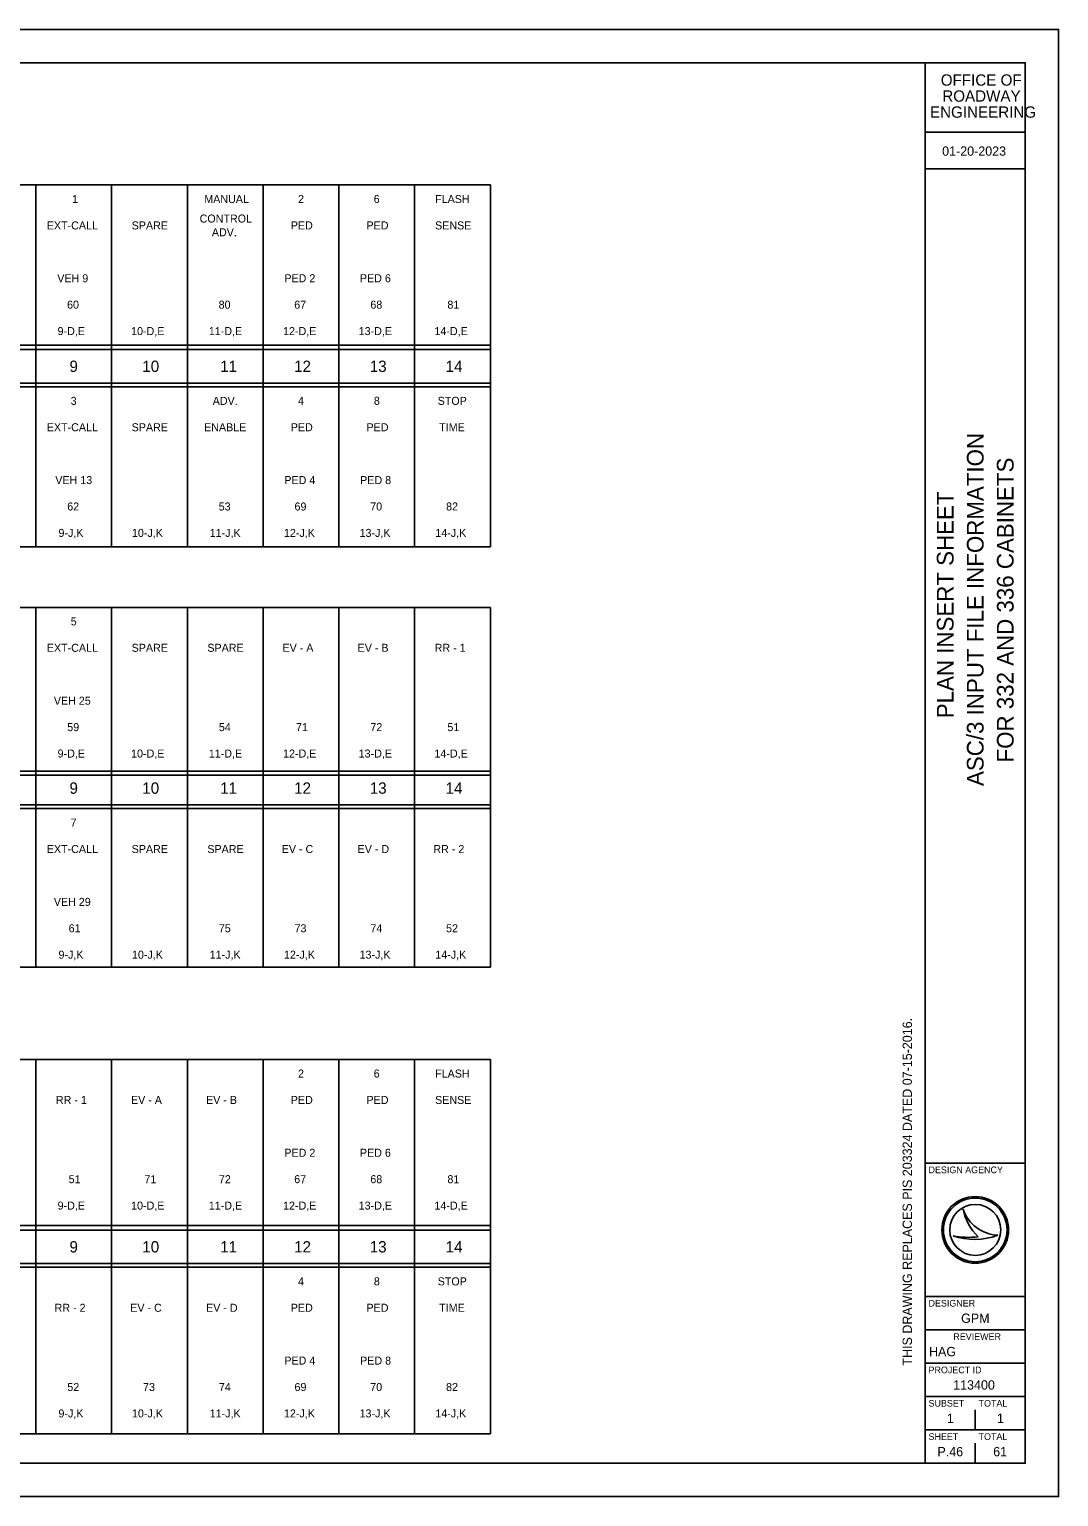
# Model space of a CAD drawing. Extents: x 0 to 34, y -1.2 to 22.
# Drawn here: x 18.57 to 34, y 0 to 22 of the extents above; entities that cross this region are included whole.
import ezdxf

# ---------------------------------------------------------------- set-up
doc = ezdxf.new("R2010")
doc.units = 0
for name, color, linetype in [('SH_Border', 7, 'Continuous'), ('SH_Cut_Line', 7, 'Continuous'), ('SH_Data', 7, 'Continuous'), ('SH_Text', 7, 'Continuous'), ('ST_Text', 7, 'Continuous')]:
    doc.layers.add(name, color=color, linetype=linetype)

msp = doc.modelspace()

# ---------------------------------------------------------------- linework, layer by layer
at = {"layer": 'SH_Border'}
for p, q in [((32, 0.5), (32, 21.5)), ((32, 5), (33.5, 5)), ((32, 3), (33.5, 3)), ((32, 2.5), (33.5, 2.5)), ((32, 2), (33.5, 2)), ((32, 1.5), (33.5, 1.5)), ((32, 1), (33.5, 1))]:
    msp.add_line(p, q, dxfattribs=at)
msp.add_lwpolyline([(1.5, 21.5), (33.5, 21.5), (33.5, 0.5), (1.5, 0.5)], close=True, dxfattribs=at)
at = {"layer": 'SH_Cut_Line'}
msp.add_lwpolyline([(0, 0), (34, 0), (34, 22), (0, 22)], close=True, dxfattribs=at)
at = {"layer": 'SH_Data'}
for p, q in [((32.567, 4.31), (32.567, 4.31)), ((32.75, 4), (32.75, 4)), ((32.417, 3.91), (32.417, 3.91)), ((33.087, 3.919), (33.087, 3.919)), ((32.75, 1), (32.75, 1.3)), ((32.375, 0.675), (32.375, 0.675)), ((32.75, 0.5), (32.75, 0.8))]:
    msp.add_line(p, q, dxfattribs=at)
for radius in [0.5, 0.477, 0.477, 0.382]:
    msp.add_circle((32.75, 4), radius, dxfattribs=at)
for centre, radius, start, end in [((33.116, 4.498), 0.58, 198.9257, 198.9319), ((33.347, 4.47), 0.796, 191.6379, 191.6421), ((33.116, 4.498), 0.58, 198.9319, 267.1657), ((33.347, 4.47), 0.796, 191.6421, 226.0947), ((32.739, 4.87), 1.013, 251.4576, 290.0832), ((32.648, 5.154), 1.266, 259.4964, 259.4995), ((32.739, 4.87), 1.013, 251.4527, 251.4576), ((32.648, 5.154), 1.266, 259.4995, 276.6672)]:
    msp.add_arc(centre, radius, start, end, dxfattribs=at)
at = {"layer": 'SH_Text'}
for p, q in [((32, 20.456), (33.5, 20.456)), ((32, 19.909), (33.5, 19.909))]:
    msp.add_line(p, q, dxfattribs=at)
at = {"layer": 'ST_Text'}
for p, q in [((25.482, 19.667), (5.77, 19.667)), ((18.67, 14.239), (18.67, 19.667)), ((19.805, 14.239), (19.805, 19.667)), ((20.941, 14.239), (20.941, 19.667)), ((22.076, 14.239), (22.076, 19.667)), ((23.212, 14.239), (23.212, 19.667)), ((24.347, 14.239), (24.347, 19.667)), ((25.482, 14.239), (25.482, 19.667)), ((25.482, 17.266), (5.77, 17.266)), ((25.482, 17.199), (5.77, 17.199)), ((25.482, 16.697), (5.77, 16.697)), ((23.945, 16.641), (5.77, 16.641)), ((25.482, 16.641), (5.77, 16.641)), ((25.482, 14.239), (5.77, 14.239)), ((23.945, 13.333), (5.77, 13.333)), ((25.482, 13.333), (5.77, 13.333)), ((18.67, 7.939), (18.67, 13.333)), ((19.805, 7.939), (19.805, 13.333)), ((20.941, 7.939), (20.941, 13.333)), ((22.076, 7.939), (22.076, 13.333)), ((23.212, 7.939), (23.212, 13.333)), ((24.347, 7.939), (24.347, 13.333)), ((25.482, 7.939), (25.482, 13.333)), ((25.482, 10.876), (5.77, 10.876)), ((25.482, 10.819), (5.77, 10.819)), ((25.482, 10.373), (5.77, 10.373)), ((25.482, 10.317), (5.77, 10.317)), ((25.482, 7.939), (5.77, 7.939)), ((25.482, 6.555), (5.77, 6.555)), ((18.67, 0.94), (18.67, 6.555)), ((19.805, 0.94), (19.805, 6.555)), ((20.941, 0.94), (20.941, 6.555)), ((22.076, 0.94), (22.076, 6.555)), ((23.212, 0.94), (23.212, 6.555)), ((24.347, 0.94), (24.347, 6.555)), ((25.482, 0.94), (25.482, 6.555)), ((25.482, 4.064), (5.77, 4.064)), ((25.482, 3.998), (5.77, 3.998)), ((25.482, 3.495), (5.77, 3.495)), ((25.482, 3.439), (5.77, 3.439)), ((25.482, 0.94), (5.77, 0.94))]:
    msp.add_line(p, q, dxfattribs=at)

# ---------------------------------------------------------------- texts
at = {"layer": 'SH_Data'}
for s, p in [('ASC/3 INPUT FILE INFORMATION', (32.875, 10.655)), ('FOR 332 AND 336 CABINETS', (33.325, 11.008)), ('PLAN INSERT SHEET', (32.425, 11.671))]:
    msp.add_text(s, height=0.25, rotation=90, dxfattribs=at).set_placement(p)
for s, height, p in [('DESIGN AGENCY', 0.1, (32.05, 4.85)), ('DESIGNER', 0.1, (32.05, 2.85)), ('GPM', 0.14, (32.538, 2.605)), ('REVIEWER', 0.1, (32.422, 2.35)), ('HAG', 0.14, (32.057, 2.105)), ('PROJECT ID', 0.1, (32.05, 1.85)), ('113400', 0.14, (32.419, 1.605)), ('SUBSET', 0.1, (32.05, 1.35)), ('TOTAL', 0.1, (32.8, 1.35)), ('1', 0.14, (32.325, 1.105)), ('1', 0.14, (33.075, 1.105)), ('SHEET', 0.1, (32.05, 0.85)), ('TOTAL', 0.1, (32.8, 0.85)), ('P.46', 0.14, (32.183, 0.605)), ('61', 0.14, (33.019, 0.605))]:
    msp.add_text(s, height=height, dxfattribs=at).set_placement(p)
at = {"layer": 'ST_Text'}
for s, height, p in [('OFFICE OF', 0.17, (32.233, 21.155)), ('ROADWAY', 0.17, (32.256, 20.915)), ('ENGINEERING', 0.17, (32.071, 20.675)), ('01-20-2023', 0.14, (32.254, 20.105)), ('1', 0.12, (19.213, 19.396)), ('MANUAL', 0.12, (21.194, 19.396)), ('2', 0.12, (22.599, 19.396)), ('6', 0.12, (23.733, 19.396)), ('FLASH', 0.12, (24.654, 19.396)), ('CONTROL', 0.12, (21.124, 19.103)), ('EXT-CALL', 0.12, (18.833, 19)), ('SPARE', 0.12, (20.105, 19)), ('ADV.', 0.12, (21.307, 18.897)), ('PED', 0.12, (22.49, 19)), ('PED', 0.12, (23.625, 19)), ('SENSE', 0.12, (24.654, 19)), ('VEH 9', 0.12, (18.99, 18.208)), ('PED 2', 0.12, (22.394, 18.208)), ('PED 6', 0.12, (23.527, 18.208)), ('60', 0.12, (19.137, 17.812)), ('80', 0.12, (21.409, 17.812)), ('67', 0.12, (22.542, 17.812)), ('68', 0.12, (23.683, 17.812)), ('81', 0.12, (24.838, 17.812)), ('9-D,E', 0.12, (18.995, 17.416)), ('10-D,E', 0.12, (20.097, 17.416)), ('11-D,E', 0.12, (21.262, 17.416)), ('12-D,E', 0.12, (22.375, 17.416)), ('13-D,E', 0.12, (23.508, 17.416)), ('14-D,E', 0.12, (24.644, 17.416)), ('9', 0.17, (19.173, 16.863)), ('10', 0.17, (20.265, 16.863)), ('11', 0.17, (21.433, 16.863)), ('12', 0.17, (22.54, 16.863)), ('13', 0.17, (23.674, 16.863)), ('14', 0.17, (24.812, 16.863)), ('3', 0.12, (19.191, 16.37)), ('ADV.', 0.12, (21.32, 16.37)), ('4', 0.12, (22.599, 16.37)), ('8', 0.12, (23.736, 16.37)), ('STOP', 0.12, (24.692, 16.37)), ('EXT-CALL', 0.12, (18.833, 15.974)), ('SPARE', 0.12, (20.105, 15.974)), ('ENABLE', 0.12, (21.191, 15.974)), ('PED', 0.12, (22.49, 15.974)), ('PED', 0.12, (23.625, 15.974)), ('TIME', 0.12, (24.715, 15.974)), ('VEH 13', 0.12, (18.961, 15.182)), ('PED 4', 0.12, (22.394, 15.182)), ('PED 8', 0.12, (23.53, 15.182)), ('62', 0.12, (19.14, 14.786)), ('53', 0.12, (21.41, 14.786)), ('69', 0.12, (22.546, 14.786)), ('70', 0.12, (23.681, 14.786)), ('82', 0.12, (24.818, 14.786)), ('9-J,K', 0.12, (19.008, 14.39)), ('10-J,K', 0.12, (20.11, 14.39)), ('11-J,K', 0.12, (21.275, 14.39)), ('12-J,K', 0.12, (22.388, 14.39)), ('13-J,K', 0.12, (23.521, 14.39)), ('14-J,K', 0.12, (24.657, 14.39)), ('5', 0.12, (19.192, 13.063)), ('EXT-CALL', 0.12, (18.833, 12.667)), ('SPARE', 0.12, (20.105, 12.667)), ('SPARE', 0.12, (21.24, 12.667)), ('EV - A', 0.12, (22.366, 12.667)), ('EV - B', 0.12, (23.492, 12.667)), ('RR - 1', 0.12, (24.647, 12.667)), ('VEH 25', 0.12, (18.939, 11.874)), ('59', 0.12, (19.14, 11.478)), ('54', 0.12, (21.412, 11.478)), ('71', 0.12, (22.568, 11.478)), ('72', 0.12, (23.683, 11.478)), ('51', 0.12, (24.838, 11.478)), ('9-D,E', 0.12, (18.995, 11.082)), ('10-D,E', 0.12, (20.097, 11.082)), ('11-D,E', 0.12, (21.262, 11.082)), ('12-D,E', 0.12, (22.375, 11.082)), ('13-D,E', 0.12, (23.508, 11.082)), ('14-D,E', 0.12, (24.644, 11.082)), ('9', 0.17, (19.173, 10.539)), ('10', 0.17, (20.265, 10.539)), ('11', 0.17, (21.433, 10.539)), ('12', 0.17, (22.54, 10.539)), ('13', 0.17, (23.674, 10.539)), ('14', 0.17, (24.812, 10.539)), ('7', 0.12, (19.189, 10.046)), ('EXT-CALL', 0.12, (18.833, 9.65)), ('SPARE', 0.12, (20.105, 9.65)), ('SPARE', 0.12, (21.24, 9.65)), ('EV - C', 0.12, (22.355, 9.65)), ('EV - D', 0.12, (23.492, 9.65)), ('RR - 2', 0.12, (24.627, 9.65)), ('VEH 29', 0.12, (18.939, 8.858)), ('61', 0.12, (19.16, 8.462)), ('75', 0.12, (21.412, 8.462)), ('73', 0.12, (22.547, 8.462)), ('74', 0.12, (23.684, 8.462)), ('52', 0.12, (24.818, 8.462)), ('9-J,K', 0.12, (19.008, 8.066)), ('10-J,K', 0.12, (20.11, 8.066)), ('11-J,K', 0.12, (21.275, 8.066)), ('12-J,K', 0.12, (22.388, 8.066)), ('13-J,K', 0.12, (23.521, 8.066)), ('14-J,K', 0.12, (24.657, 8.066)), ('2', 0.12, (22.599, 6.284)), ('6', 0.12, (23.733, 6.284)), ('FLASH', 0.12, (24.654, 6.284)), ('RR - 1', 0.12, (18.97, 5.888)), ('EV - A', 0.12, (20.095, 5.888)), ('EV - B', 0.12, (21.221, 5.888)), ('PED', 0.12, (22.49, 5.888)), ('PED', 0.12, (23.625, 5.888)), ('SENSE', 0.12, (24.654, 5.888)), ('PED 2', 0.12, (22.394, 5.096)), ('PED 6', 0.12, (23.527, 5.096)), ('51', 0.12, (19.161, 4.7)), ('71', 0.12, (20.297, 4.7)), ('72', 0.12, (21.413, 4.7)), ('67', 0.12, (22.542, 4.7)), ('68', 0.12, (23.683, 4.7)), ('81', 0.12, (24.838, 4.7)), ('9-D,E', 0.12, (18.995, 4.304)), ('10-D,E', 0.12, (20.097, 4.304)), ('11-D,E', 0.12, (21.262, 4.304)), ('12-D,E', 0.12, (22.375, 4.304)), ('13-D,E', 0.12, (23.508, 4.304)), ('14-D,E', 0.12, (24.644, 4.304)), ('9', 0.17, (19.173, 3.661)), ('10', 0.17, (20.265, 3.661)), ('11', 0.17, (21.433, 3.661)), ('12', 0.17, (22.54, 3.661)), ('13', 0.17, (23.674, 3.661)), ('14', 0.17, (24.812, 3.661)), ('4', 0.12, (22.599, 3.168)), ('8', 0.12, (23.736, 3.168)), ('STOP', 0.12, (24.692, 3.168)), ('RR - 2', 0.12, (18.95, 2.772)), ('EV - C', 0.12, (20.084, 2.772)), ('EV - D', 0.12, (21.221, 2.772)), ('PED', 0.12, (22.49, 2.772)), ('PED', 0.12, (23.625, 2.772)), ('TIME', 0.12, (24.715, 2.772)), ('PED 4', 0.12, (22.394, 1.98)), ('PED 8', 0.12, (23.53, 1.98)), ('52', 0.12, (19.141, 1.584)), ('73', 0.12, (20.276, 1.584)), ('74', 0.12, (21.413, 1.584)), ('69', 0.12, (22.546, 1.584)), ('70', 0.12, (23.681, 1.584)), ('82', 0.12, (24.818, 1.584)), ('9-J,K', 0.12, (19.008, 1.188)), ('10-J,K', 0.12, (20.11, 1.188)), ('11-J,K', 0.12, (21.275, 1.188)), ('12-J,K', 0.12, (22.388, 1.188)), ('13-J,K', 0.12, (23.521, 1.188)), ('14-J,K', 0.12, (24.657, 1.188))]:
    msp.add_text(s, height=height, dxfattribs=at).set_placement(p)
msp.add_text('THIS DRAWING REPLACES PIS 203324 DATED 07-15-2016.', height=0.14, rotation=90, dxfattribs=at).set_placement((31.801, 1.965))

doc.saveas('drawing.dxf')
